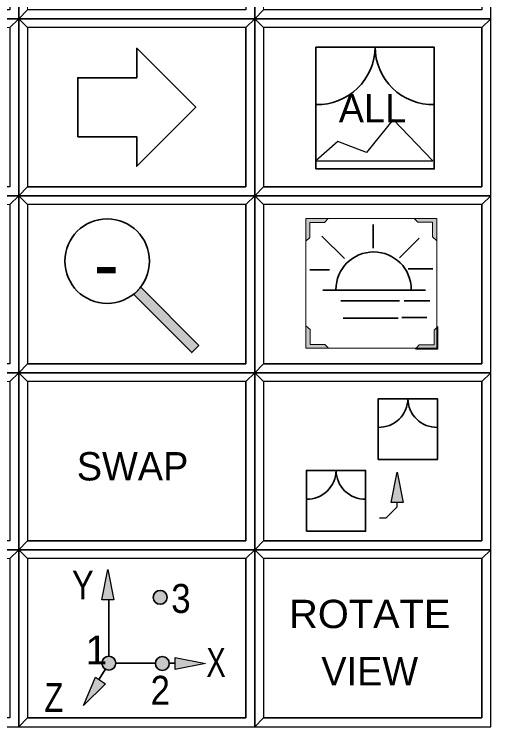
# Model space of a CAD drawing. Extents: x 95906.9 to 95918.9, y 90964.8 to 90972.9.
# Drawn here: x 95913.825 to 95914.632, y 90970.562 to 90971.769 of the extents above; entities that cross this region are included whole.
import ezdxf
from ezdxf.enums import TextEntityAlignment as Align

# ---------------------------------------------------------------- set-up
doc = ezdxf.new("R2010")
doc.units = 0
doc.header["$LTSCALE"] = 0.019
doc.linetypes.add('DOTTED', pattern=[1.5, 0.3, -1.2])
for name, color, linetype, lineweight in [('1', 7, 'Continuous', 25), ('11', 7, 'Continuous', 25), ('2', 7, 'Continuous', 13), ('3', 7, 'Continuous', 25), ('4', 7, 'Continuous', 35), ('6', 7, 'Continuous', 35)]:
    doc.layers.add(name, color=color, linetype=linetype, lineweight=lineweight)

msp = doc.modelspace()

# ---------------------------------------------------------------- hatches: boundary and pattern name
at = {"layer": '6'}
for points in [[(95914.357, 90971.4231), (95914.3191, 90971.4231), (95914.3191, 90971.3846), (95914.3255, 90971.391), (95914.3255, 90971.416), (95914.3505, 90971.416)], [(95914.5409, 90971.3852), (95914.5409, 90971.4231), (95914.5024, 90971.4231), (95914.5088, 90971.4167), (95914.5338, 90971.4167), (95914.5338, 90971.3917)], [(95914.0272, 90971.2945), (95914.1257, 90971.1959), (95914.1376, 90971.2078), (95914.0391, 90971.3064)], [(95914.3191, 90971.2412), (95914.3191, 90971.2033), (95914.3576, 90971.2033), (95914.3512, 90971.2097), (95914.3262, 90971.2097), (95914.3262, 90971.2347)], [(95914.5047, 90971.2018), (95914.5426, 90971.2018), (95914.5426, 90971.2403), (95914.5362, 90971.2339), (95914.5362, 90971.2089), (95914.5112, 90971.2089)], [(95914.4634, 90970.9419), (95914.4736, 90970.9931), (95914.4838, 90970.9419)], [(95913.973, 90970.7769), (95913.9832, 90970.8281), (95913.9934, 90970.7769)], [(95914.084, 90970.781, 1), (95914.0604, 90970.781, 1)], [(95913.997, 90970.6694, 1), (95913.9734, 90970.6694, 1)], [(95914.0875, 90970.669, 1), (95914.0639, 90970.669, 1)], [(95914.0976, 90970.6792), (95914.1488, 90970.669), (95914.0976, 90970.6588)], [(95913.9793, 90970.6346), (95913.9422, 90970.5978), (95913.9624, 90970.646)]]:
    msp.add_hatch(color=256, dxfattribs=at).paths.add_polyline_path(points)

# ---------------------------------------------------------------- linework, layer by layer
at = {"layer": '1'}
for points in [[(95913.4323, 90971.7617), (95913.8323, 90971.7617), (95913.8323, 90972.0617), (95913.4323, 90972.0617)], [(95913.8323, 90971.7617), (95914.2323, 90971.7617), (95914.2323, 90972.0617), (95913.8323, 90972.0617)], [(95914.2323, 90971.7617), (95914.6323, 90971.7617), (95914.6323, 90972.0617), (95914.2323, 90972.0617)], [(95913.4323, 90971.4617), (95913.8323, 90971.4617), (95913.8323, 90971.7617), (95913.4323, 90971.7617)], [(95913.8323, 90971.4617), (95914.2323, 90971.4617), (95914.2323, 90971.7617), (95913.8323, 90971.7617)], [(95914.2323, 90971.4617), (95914.6323, 90971.4617), (95914.6323, 90971.7617), (95914.2323, 90971.7617)], [(95913.4323, 90971.1617), (95913.8323, 90971.1617), (95913.8323, 90971.4617), (95913.4323, 90971.4617)], [(95913.8323, 90971.1617), (95914.2323, 90971.1617), (95914.2323, 90971.4617), (95913.8323, 90971.4617)], [(95914.2323, 90971.1617), (95914.6323, 90971.1617), (95914.6323, 90971.4617), (95914.2323, 90971.4617)], [(95913.4323, 90970.8617), (95913.8323, 90970.8617), (95913.8323, 90971.1617), (95913.4323, 90971.1617)], [(95913.8323, 90970.8617), (95914.2323, 90970.8617), (95914.2323, 90971.1617), (95913.8323, 90971.1617)], [(95914.2323, 90970.8617), (95914.6323, 90970.8617), (95914.6323, 90971.1617), (95914.2323, 90971.1617)], [(95913.4323, 90970.5617), (95913.8323, 90970.5617), (95913.8323, 90970.8617), (95913.4323, 90970.8617)], [(95913.8323, 90970.5617), (95914.2323, 90970.5617), (95914.2323, 90970.8617), (95913.8323, 90970.8617)], [(95914.2323, 90970.5617), (95914.6323, 90970.5617), (95914.6323, 90970.8617), (95914.2323, 90970.8617)]]:
    msp.add_lwpolyline(points, close=True, dxfattribs=at)
at = {"layer": '11'}
for points in [[(95913.8473, 90971.4767), (95914.2173, 90971.4767), (95914.2173, 90971.7467), (95913.8473, 90971.7467)], [(95914.2473, 90971.4767), (95914.6173, 90971.4767), (95914.6173, 90971.7467), (95914.2473, 90971.7467)], [(95913.8473, 90971.1767), (95914.2173, 90971.1767), (95914.2173, 90971.4467), (95913.8473, 90971.4467)], [(95914.2473, 90971.1767), (95914.6173, 90971.1767), (95914.6173, 90971.4467), (95914.2473, 90971.4467)], [(95913.8473, 90970.8767), (95914.2173, 90970.8767), (95914.2173, 90971.1467), (95913.8473, 90971.1467)], [(95914.2473, 90970.8767), (95914.6173, 90970.8767), (95914.6173, 90971.1467), (95914.2473, 90971.1467)], [(95913.8473, 90970.5767), (95914.2173, 90970.5767), (95914.2173, 90970.8467), (95913.8473, 90970.8467)], [(95914.2473, 90970.5767), (95914.6173, 90970.5767), (95914.6173, 90970.8467), (95914.2473, 90970.8467)]]:
    msp.add_lwpolyline(points, close=True, dxfattribs=at)
at = {"layer": '2'}
for points in [[(95913.8323, 90972.0617), (95913.8323, 90971.7617), (95913.8473, 90971.7767), (95913.8473, 90972.0467), (95914.2173, 90972.0467), (95914.2323, 90972.0617)], [(95914.2323, 90972.0617), (95914.2323, 90971.7617), (95914.2473, 90971.7767), (95914.2473, 90972.0467), (95914.6173, 90972.0467), (95914.6323, 90972.0617)], [(95913.4323, 90971.7617), (95913.4323, 90971.4617), (95913.4473, 90971.4767), (95913.4473, 90971.7467), (95913.8173, 90971.7467), (95913.8323, 90971.7617)], [(95913.8323, 90971.7617), (95913.8323, 90971.4617), (95913.8473, 90971.4767), (95913.8473, 90971.7467), (95914.2173, 90971.7467), (95914.2323, 90971.7617)], [(95914.2323, 90971.7617), (95914.2323, 90971.4617), (95914.2473, 90971.4767), (95914.2473, 90971.7467), (95914.6173, 90971.7467), (95914.6323, 90971.7617)], [(95913.4323, 90971.4617), (95913.4323, 90971.1617), (95913.4473, 90971.1767), (95913.4473, 90971.4467), (95913.8173, 90971.4467), (95913.8323, 90971.4617)], [(95913.8323, 90971.4617), (95913.8323, 90971.1617), (95913.8473, 90971.1767), (95913.8473, 90971.4467), (95914.2173, 90971.4467), (95914.2323, 90971.4617)], [(95914.2323, 90971.4617), (95914.2323, 90971.1617), (95914.2473, 90971.1767), (95914.2473, 90971.4467), (95914.6173, 90971.4467), (95914.6323, 90971.4617)], [(95913.4323, 90971.1617), (95913.4323, 90970.8617), (95913.4473, 90970.8767), (95913.4473, 90971.1467), (95913.8173, 90971.1467), (95913.8323, 90971.1617)], [(95913.8323, 90971.1617), (95913.8323, 90970.8617), (95913.8473, 90970.8767), (95913.8473, 90971.1467), (95914.2173, 90971.1467), (95914.2323, 90971.1617)], [(95914.2323, 90971.1617), (95914.2323, 90970.8617), (95914.2473, 90970.8767), (95914.2473, 90971.1467), (95914.6173, 90971.1467), (95914.6323, 90971.1617)], [(95913.4323, 90970.8617), (95913.4323, 90970.5617), (95913.4473, 90970.5767), (95913.4473, 90970.8467), (95913.8173, 90970.8467), (95913.8323, 90970.8617)], [(95913.8323, 90970.8617), (95913.8323, 90970.5617), (95913.8473, 90970.5767), (95913.8473, 90970.8467), (95914.2173, 90970.8467), (95914.2323, 90970.8617)], [(95914.2323, 90970.8617), (95914.2323, 90970.5617), (95914.2473, 90970.5767), (95914.2473, 90970.8467), (95914.6173, 90970.8467), (95914.6323, 90970.8617)]]:
    msp.add_lwpolyline(points, close=True, dxfattribs=at)
at = {"layer": '3'}
for points in [[(95913.4323, 90971.7617), (95913.8323, 90971.7617), (95913.8323, 90972.0617), (95913.8173, 90972.0467), (95913.8173, 90971.7767), (95913.4473, 90971.7767)], [(95913.8323, 90971.7617), (95914.2323, 90971.7617), (95914.2323, 90972.0617), (95914.2173, 90972.0467), (95914.2173, 90971.7767), (95913.8473, 90971.7767)], [(95914.2323, 90971.7617), (95914.6323, 90971.7617), (95914.6323, 90972.0617), (95914.6173, 90972.0467), (95914.6173, 90971.7767), (95914.2473, 90971.7767)], [(95913.4323, 90971.4617), (95913.8323, 90971.4617), (95913.8323, 90971.7617), (95913.8173, 90971.7467), (95913.8173, 90971.4767), (95913.4473, 90971.4767)], [(95913.8323, 90971.4617), (95914.2323, 90971.4617), (95914.2323, 90971.7617), (95914.2173, 90971.7467), (95914.2173, 90971.4767), (95913.8473, 90971.4767)], [(95914.2323, 90971.4617), (95914.6323, 90971.4617), (95914.6323, 90971.7617), (95914.6173, 90971.7467), (95914.6173, 90971.4767), (95914.2473, 90971.4767)], [(95913.4323, 90971.1617), (95913.8323, 90971.1617), (95913.8323, 90971.4617), (95913.8173, 90971.4467), (95913.8173, 90971.1767), (95913.4473, 90971.1767)], [(95913.8323, 90971.1617), (95914.2323, 90971.1617), (95914.2323, 90971.4617), (95914.2173, 90971.4467), (95914.2173, 90971.1767), (95913.8473, 90971.1767)], [(95914.2323, 90971.1617), (95914.6323, 90971.1617), (95914.6323, 90971.4617), (95914.6173, 90971.4467), (95914.6173, 90971.1767), (95914.2473, 90971.1767)], [(95913.4323, 90970.8617), (95913.8323, 90970.8617), (95913.8323, 90971.1617), (95913.8173, 90971.1467), (95913.8173, 90970.8767), (95913.4473, 90970.8767)], [(95913.8323, 90970.8617), (95914.2323, 90970.8617), (95914.2323, 90971.1617), (95914.2173, 90971.1467), (95914.2173, 90970.8767), (95913.8473, 90970.8767)], [(95914.2323, 90970.8617), (95914.6323, 90970.8617), (95914.6323, 90971.1617), (95914.6173, 90971.1467), (95914.6173, 90970.8767), (95914.2473, 90970.8767)], [(95913.4323, 90970.5617), (95913.8323, 90970.5617), (95913.8323, 90970.8617), (95913.8173, 90970.8467), (95913.8173, 90970.5767), (95913.4473, 90970.5767)], [(95913.8323, 90970.5617), (95914.2323, 90970.5617), (95914.2323, 90970.8617), (95914.2173, 90970.8467), (95914.2173, 90970.5767), (95913.8473, 90970.5767)], [(95914.2323, 90970.5617), (95914.6323, 90970.5617), (95914.6323, 90970.8617), (95914.6173, 90970.8467), (95914.6173, 90970.5767), (95914.2473, 90970.5767)]]:
    msp.add_lwpolyline(points, close=True, dxfattribs=at)
at = {"layer": '4'}
for p, q in [((95913.8473, 90971.7467), (95913.8323, 90971.7617)), ((95914.2473, 90971.7467), (95914.2323, 90971.7617)), ((95913.8473, 90971.4467), (95913.8323, 90971.4617)), ((95914.2473, 90971.4467), (95914.2323, 90971.4617)), ((95913.8473, 90971.1467), (95913.8323, 90971.1617)), ((95914.2473, 90971.1467), (95914.2323, 90971.1617)), ((95913.8473, 90970.8467), (95913.8323, 90970.8617)), ((95914.2473, 90970.8467), (95914.2323, 90970.8617))]:
    msp.add_line(p, q, dxfattribs=at)
at = {"layer": '6'}
for p, q in [((95914.4328, 90971.3725), (95914.4328, 90971.413)), ((95914.3842, 90971.3552), (95914.3462, 90971.3932)), ((95914.4774, 90971.3563), (95914.5108, 90971.3897)), ((95914.3589, 90971.336), (95914.3255, 90971.336)), ((95914.4926, 90971.338), (95914.5341, 90971.338)), ((95914.3477, 90971.3016), (95914.5219, 90971.3016)), ((95914.3781, 90971.2833), (95914.4774, 90971.2833)), ((95914.3822, 90971.254), (95914.4754, 90971.254)), ((95913.9852, 90970.7769), (95913.9852, 90970.6808)), ((95913.9975, 90970.6694), (95914.0642, 90970.6694)), ((95914.0887, 90970.6694), (95914.0976, 90970.6694)), ((95913.9787, 90970.6586), (95913.9688, 90970.6421))]:
    msp.add_line(p, q, dxfattribs=at)
at = {"layer": '6', "linetype": 'DOTTED'}
for p, q in [((95914.4855, 90971.2833), (95914.529, 90971.2833)), ((95914.4814, 90971.255), (95914.524, 90971.255))]:
    msp.add_line(p, q, dxfattribs=at)
at = {"layer": '6'}
for points in [[(95913.9323, 90971.5617), (95914.0323, 90971.5617), (95914.0323, 90971.5117), (95914.1323, 90971.6117), (95914.0323, 90971.7117), (95914.0323, 90971.6617), (95913.9323, 90971.6617)], [(95914.336, 90971.5072), (95914.5365, 90971.5072), (95914.5365, 90971.7134), (95914.336, 90971.7134)], [(95914.0272, 90971.2945), (95914.1257, 90971.1959), (95914.1376, 90971.2078), (95914.0391, 90971.3064)], [(95914.4417, 90971.0146), (95914.5419, 90971.0146), (95914.5419, 90971.1177), (95914.4417, 90971.1177)], [(95914.32, 90970.8929), (95914.4202, 90970.8929), (95914.4202, 90970.996), (95914.32, 90970.996)]]:
    msp.add_lwpolyline(points, close=True, dxfattribs=at)
at = {"layer": '6', "lineweight": 25}
for points in [[(95914.3357, 90971.5207), (95914.5341, 90971.5207), (95914.4668, 90971.5909), (95914.4217, 90971.5351), (95914.373, 90971.5537)], [(95914.4634, 90970.9419), (95914.4736, 90970.9931), (95914.4838, 90970.9419)], [(95913.973, 90970.7769), (95913.9832, 90970.8281), (95913.9934, 90970.7769)], [(95914.0976, 90970.6792), (95914.1488, 90970.669), (95914.0976, 90970.6588)], [(95913.9793, 90970.6346), (95913.9422, 90970.5978), (95913.9624, 90970.646)]]:
    msp.add_lwpolyline(points, close=True, dxfattribs=at)
at = {"layer": '6', "lineweight": 13}
for points in [[(95914.3191, 90971.2033), (95914.5409, 90971.2033), (95914.5409, 90971.4231), (95914.3191, 90971.4231)], [(95914.357, 90971.4231), (95914.3191, 90971.4231), (95914.3191, 90971.3846), (95914.3255, 90971.391), (95914.3255, 90971.416), (95914.3505, 90971.416)], [(95914.5409, 90971.3852), (95914.5409, 90971.4231), (95914.5024, 90971.4231), (95914.5088, 90971.4167), (95914.5338, 90971.4167), (95914.5338, 90971.3917)], [(95914.3191, 90971.2412), (95914.3191, 90971.2033), (95914.3576, 90971.2033), (95914.3512, 90971.2097), (95914.3262, 90971.2097), (95914.3262, 90971.2347)], [(95914.5047, 90971.2018), (95914.5426, 90971.2018), (95914.5426, 90971.2403), (95914.5362, 90971.2339), (95914.5362, 90971.2089), (95914.5112, 90971.2089)]]:
    msp.add_lwpolyline(points, close=True, dxfattribs=at)
at = {"layer": '6', "lineweight": 25}
msp.add_lwpolyline([(95914.4435, 90970.9158), (95914.455, 90970.9158), (95914.4736, 90970.9344), (95914.4736, 90970.9419)], dxfattribs=at)
at = {"layer": '6'}
for centre, radius in [((95913.9823, 90971.3508), 0.0716), ((95914.0722, 90970.781), 0.0118), ((95913.9852, 90970.6694), 0.0118), ((95914.0757, 90970.669), 0.0118)]:
    msp.add_circle(centre, radius, dxfattribs=at)
for centre, radius, start, end in [((95914.3383, 90971.714), 0.098, 268.6755, 359.6437), ((95914.5343, 90971.714), 0.098, 180.3563, 271.3245), ((95914.4338, 90971.3026), 0.0638, 0, 180), ((95914.4428, 90971.118), 0.049, 268.6755, 359.6437), ((95914.5409, 90971.118), 0.049, 180.3563, 271.3245), ((95914.3211, 90970.9963), 0.049, 268.6755, 359.6437), ((95914.4192, 90970.9963), 0.049, 180.3563, 271.3245)]:
    msp.add_arc(centre, radius, start, end, dxfattribs=at)

# ---------------------------------------------------------------- texts
for s, height, p in [('ALL', 0.048, (95914.4318, 90971.5859)), ('-', 0.096, (95913.9808, 90971.2983)), ('SWAP', 0.048, (95914.0253, 90970.9791)), ('1', 0.0491, (95913.9641, 90970.6672)), ('VIEW', 0.04799, (95914.4272, 90970.6319))]:
    msp.add_text(s, height=height, dxfattribs=at).set_placement(p, align=Align.CENTER)
for s, height, width, p in [('Y', 0.0491, 0.85, (95913.941, 90970.7774)), ('3', 0.0491, 0.9, (95914.1073, 90970.7546)), ('ROTATE', 0.04799, 1.05, (95914.4273, 90970.7289)), ('X', 0.0491, 0.75, (95914.1668, 90970.6462)), ('2', 0.0491, 0.9, (95914.0722, 90970.5989)), ('Z', 0.0491, 0.8, (95913.892, 90970.5867))]:
    msp.add_text(s, height=height, dxfattribs=dict(at, width=width)).set_placement(p, align=Align.CENTER)

doc.saveas('drawing.dxf')
